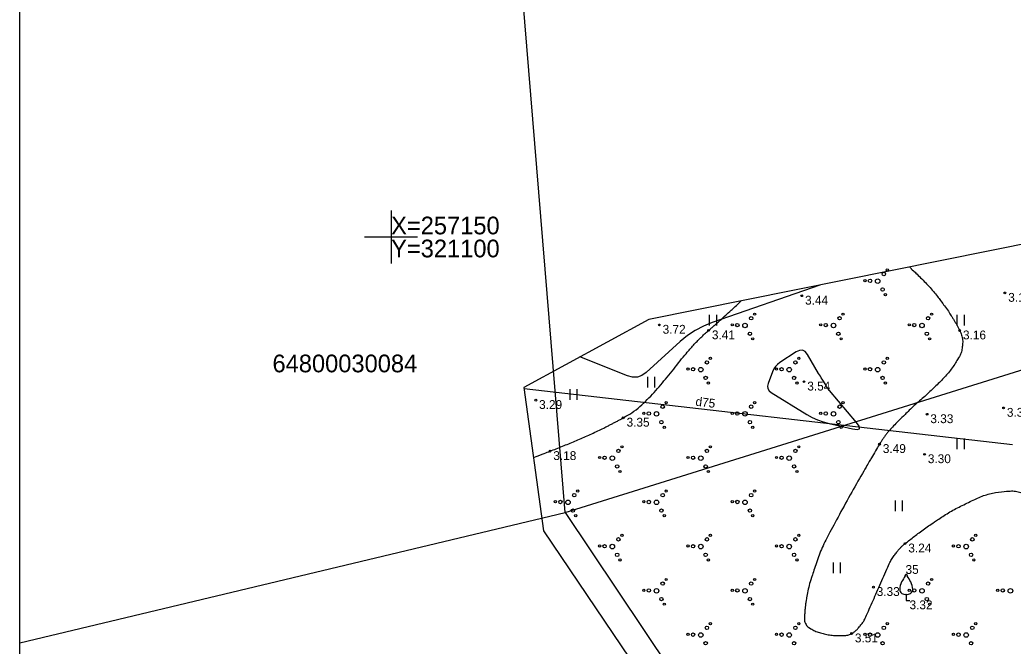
# Model space of a CAD drawing. Extents: x 321079 to 321220, y 257030 to 257220.
# Drawn here: x 321079 to 321135.2, y 257126.9 to 257162.3 of the extents above; entities that cross this region are included whole.
import ezdxf

# ---------------------------------------------------------------- set-up
doc = ezdxf.new("R2010")
doc.units = 0
for name, color, linetype in [('DREN_VADP_####_####_#', 7, 'Continuous'), ('DREN_VADP_####_TKST_#', 7, 'Continuous'), ('GEOD_ELEM_####_####_#', 7, 'Continuous'), ('GEOD_KORD_####_TKST_#', 7, 'Continuous'), ('RAMI_PLAN_####_TKST_#', 7, 'Continuous'), ('RAMI_UZMR_####_####_#', 7, 'Continuous'), ('RELJ_AATZ_####_TKST_#', 7, 'Continuous'), ('RELJ_ELEM_####_####_#', 7, 'Continuous'), ('RELJ_HORZ_PUSH_####_#', 7, 'Continuous'), ('ROBZ_KADS_####_TKST_#', 7, 'Continuous'), ('ROBZ_UZMR_####_####_#', 7, 'Continuous'), ('TERT_DIAM_####_TKST_#', 7, 'Continuous'), ('TERT_ELEM_####_####_#', 7, 'Continuous'), ('TERT_KONT_####_####_#', 7, 'Continuous')]:
    doc.layers.add(name, color=color, linetype=linetype)

msp = doc.modelspace()

# ---------------------------------------------------------------- linework, layer by layer
at = {"layer": 'DREN_VADP_####_####_#'}
msp.add_lwpolyline([(321135.115, 257138.26), (321107.511, 257141.42)], dxfattribs=at)
at = {"layer": 'GEOD_ELEM_####_####_#'}
for p, q in [((321100, 257151.5), (321100, 257150)), ((321098.5, 257150), (321100, 257150)), ((321100, 257150), (321100, 257148.5)), ((321100, 257150), (321101.5, 257150))]:
    msp.add_line(p, q, dxfattribs=at)
at = {"layer": 'RAMI_PLAN_####_TKST_#'}
msp.add_lwpolyline([(321079.019, 257029.866), (321079.019, 257219.866), (321218.314, 257219.866), (321218.314, 257029.866)], close=True, dxfattribs=at)
at = {"layer": 'RAMI_UZMR_####_####_#'}
msp.add_lwpolyline([(321107.5, 257141.5), (321108.611, 257133.395), (321131.584, 257099.382), (321150.327, 257105.322), (321177.121, 257109.842), (321183.308, 257111.386), (321177.517, 257137.442), (321172.561, 257161.05), (321156.27, 257158.872), (321156.852, 257154.517), (321139.352, 257150.329), (321114.57, 257145.337)], close=True, dxfattribs=at)
at = {"layer": 'RELJ_ELEM_####_####_#'}
for centre in [(321123.209, 257146.678), (321134.69, 257146.837), (321115.159, 257145.031), (321117.943, 257144.718), (321132.134, 257144.712), (321123.335, 257141.822), (321108.178, 257140.778), (321134.616, 257140.338), (321113.121, 257139.78), (321130.289, 257139.978), (321127.604, 257138.29), (321108.981, 257137.891), (321130.148, 257137.716), (321129.045, 257132.669), (321127.258, 257130.208), (321126.024, 257127.585)]:
    msp.add_circle(centre, 0.05, dxfattribs=at)
at = {"layer": 'RELJ_HORZ_PUSH_####_#'}
msp.add_lwpolyline([(321124.236, 257147.285), (321118.152, 257145.164), (321117.657, 257144.963), (321117.19, 257144.716), (321116.75, 257144.423), (321116.338, 257144.084), (321114.417, 257142.337), (321114.175, 257142.164), (321113.917, 257142.075), (321113.645, 257142.069), (321113.357, 257142.145), (321110.672, 257143.222)], dxfattribs=at)
msp.add_lwpolyline([(321121.273, 257141.566), (321121.29, 257141.429), (321121.361, 257141.309), (321121.485, 257141.208), (321123.499, 257139.968), (321123.796, 257139.802), (321124.103, 257139.661), (321124.421, 257139.546), (321124.749, 257139.456), (321126.083, 257139.15), (321126.347, 257139.115), (321126.473, 257139.165), (321126.46, 257139.3), (321126.308, 257139.519), (321124.783, 257141.324), (321124.723, 257141.399), (321124.666, 257141.475), (321124.611, 257141.554), (321124.56, 257141.635), (321124.361, 257141.962), (321124.311, 257142.044), (321124.262, 257142.126), (321124.212, 257142.209), (321124.163, 257142.291), (321123.529, 257143.355), (321123.397, 257143.518), (321123.246, 257143.597), (321123.075, 257143.592), (321122.885, 257143.504), (321121.971, 257142.906), (321121.834, 257142.801), (321121.719, 257142.679), (321121.625, 257142.539), (321121.553, 257142.383), (321121.307, 257141.722)], close=True, dxfattribs=at)
at = {"layer": 'ROBZ_UZMR_####_####_#'}
for p, q in [((321109.842, 257134.432), (321104.62, 257197.779)), ((321109.842, 257134.432), (321160.832, 257150.36)), ((321079.019, 257127.063), (321109.842, 257134.432)), ((321109.842, 257134.432), (321131.975, 257101.369))]:
    msp.add_line(p, q, dxfattribs=at)
at = {"layer": 'TERT_ELEM_####_####_#'}
for p, q in [((321118, 257145), (321118, 257145.6)), ((321118.4, 257145), (321118.4, 257145.6)), ((321132, 257145), (321132, 257145.6)), ((321132.4, 257145), (321132.4, 257145.6)), ((321114.5, 257141.5), (321114.5, 257142.1)), ((321114.9, 257141.5), (321114.9, 257142.1)), ((321110.119, 257140.803), (321110.119, 257141.403)), ((321110.519, 257140.803), (321110.519, 257141.403)), ((321132, 257138), (321132, 257138.6)), ((321132.4, 257138), (321132.4, 257138.6)), ((321128.5, 257134.5), (321128.5, 257135.1)), ((321128.9, 257134.5), (321128.9, 257135.1)), ((321125, 257131), (321125, 257131.6)), ((321125.4, 257131), (321125.4, 257131.6)), ((321129.112, 257129.809), (321129.112, 257129.457)), ((321129.112, 257129.457), (321129.312, 257129.457))]:
    msp.add_line(p, q, dxfattribs=at)
for centre, radius in [((321127.848, 257147.908), 0.096), ((321128.044, 257148.139), 0.064), ((321126.782, 257147.534), 0.064), ((321127.066, 257147.521), 0.096), ((321127.5, 257147.5), 0.128), ((321127.776, 257147.033), 0.096), ((321127.934, 257146.744), 0.064), ((321120.348, 257145.408), 0.096), ((321120.544, 257145.639), 0.064), ((321125.348, 257145.408), 0.096), ((321125.544, 257145.639), 0.064), ((321130.348, 257145.408), 0.096), ((321130.544, 257145.639), 0.064), ((321119.282, 257145.034), 0.064), ((321119.566, 257145.021), 0.096), ((321120, 257145), 0.128), ((321124.282, 257145.034), 0.064), ((321124.566, 257145.021), 0.096), ((321125, 257145), 0.128), ((321129.282, 257145.034), 0.064), ((321129.566, 257145.021), 0.096), ((321130, 257145), 0.128), ((321120.276, 257144.533), 0.096), ((321120.434, 257144.244), 0.064), ((321125.276, 257144.533), 0.096), ((321125.434, 257144.244), 0.064), ((321130.276, 257144.533), 0.096), ((321130.434, 257144.244), 0.064), ((321118.044, 257143.139), 0.064), ((321123.044, 257143.139), 0.064), ((321128.044, 257143.139), 0.064), ((321117.066, 257142.521), 0.096), ((321117.5, 257142.5), 0.128), ((321117.848, 257142.908), 0.096), ((321122.066, 257142.521), 0.096), ((321122.5, 257142.5), 0.128), ((321122.848, 257142.908), 0.096), ((321127.066, 257142.521), 0.096), ((321127.5, 257142.5), 0.128), ((321127.848, 257142.908), 0.096), ((321116.782, 257142.534), 0.064), ((321117.776, 257142.033), 0.096), ((321121.782, 257142.534), 0.064), ((321122.776, 257142.033), 0.096), ((321126.782, 257142.534), 0.064), ((321127.776, 257142.033), 0.096), ((321117.934, 257141.744), 0.064), ((321122.934, 257141.744), 0.064), ((321127.934, 257141.744), 0.064), ((321115.348, 257140.408), 0.096), ((321115.544, 257140.639), 0.064), ((321120.348, 257140.408), 0.096), ((321120.544, 257140.639), 0.064), ((321125.348, 257140.408), 0.096), ((321125.544, 257140.639), 0.064), ((321114.282, 257140.034), 0.064), ((321114.566, 257140.021), 0.096), ((321115, 257140), 0.128), ((321119.282, 257140.034), 0.064), ((321119.566, 257140.021), 0.096), ((321120, 257140), 0.128), ((321124.282, 257140.034), 0.064), ((321124.566, 257140.021), 0.096), ((321125, 257140), 0.128), ((321115.276, 257139.533), 0.096), ((321115.434, 257139.244), 0.064), ((321120.276, 257139.533), 0.096), ((321120.434, 257139.244), 0.064), ((321125.276, 257139.533), 0.096), ((321125.434, 257139.244), 0.064), ((321113.044, 257138.139), 0.064), ((321118.044, 257138.139), 0.064), ((321123.044, 257138.139), 0.064), ((321111.782, 257137.534), 0.064), ((321112.066, 257137.521), 0.096), ((321112.5, 257137.5), 0.128), ((321112.848, 257137.908), 0.096), ((321116.782, 257137.534), 0.064), ((321117.066, 257137.521), 0.096), ((321117.5, 257137.5), 0.128), ((321117.848, 257137.908), 0.096), ((321121.782, 257137.534), 0.064), ((321122.066, 257137.521), 0.096), ((321122.5, 257137.5), 0.128), ((321122.848, 257137.908), 0.096), ((321112.776, 257137.033), 0.096), ((321117.776, 257137.033), 0.096), ((321122.776, 257137.033), 0.096), ((321112.934, 257136.744), 0.064), ((321117.934, 257136.744), 0.064), ((321122.934, 257136.744), 0.064), ((321110.348, 257135.408), 0.096), ((321110.544, 257135.639), 0.064), ((321115.348, 257135.408), 0.096), ((321115.544, 257135.639), 0.064), ((321120.348, 257135.408), 0.096), ((321120.544, 257135.639), 0.064), ((321109.282, 257135.034), 0.064), ((321109.566, 257135.021), 0.096), ((321110, 257135), 0.128), ((321114.282, 257135.034), 0.064), ((321114.566, 257135.021), 0.096), ((321115, 257135), 0.128), ((321119.282, 257135.034), 0.064), ((321119.566, 257135.021), 0.096), ((321120, 257135), 0.128), ((321110.276, 257134.533), 0.096), ((321110.434, 257134.244), 0.064), ((321115.276, 257134.533), 0.096), ((321115.434, 257134.244), 0.064), ((321120.276, 257134.533), 0.096), ((321120.434, 257134.244), 0.064), ((321113.044, 257133.139), 0.064), ((321118.044, 257133.139), 0.064), ((321123.044, 257133.139), 0.064), ((321133.044, 257133.139), 0.064), ((321111.782, 257132.534), 0.064), ((321112.066, 257132.521), 0.096), ((321112.5, 257132.5), 0.128), ((321112.848, 257132.908), 0.096), ((321116.782, 257132.534), 0.064), ((321117.066, 257132.521), 0.096), ((321117.5, 257132.5), 0.128), ((321117.848, 257132.908), 0.096), ((321121.782, 257132.534), 0.064), ((321122.066, 257132.521), 0.096), ((321122.5, 257132.5), 0.128), ((321122.848, 257132.908), 0.096), ((321131.782, 257132.534), 0.064), ((321132.066, 257132.521), 0.096), ((321132.5, 257132.5), 0.128), ((321132.848, 257132.908), 0.096), ((321112.776, 257132.033), 0.096), ((321117.776, 257132.033), 0.096), ((321122.776, 257132.033), 0.096), ((321132.776, 257132.033), 0.096), ((321112.934, 257131.744), 0.064), ((321117.934, 257131.744), 0.064), ((321122.934, 257131.744), 0.064), ((321132.934, 257131.744), 0.064), ((321115.348, 257130.408), 0.096), ((321115.544, 257130.639), 0.064), ((321120.348, 257130.408), 0.096), ((321120.544, 257130.639), 0.064), ((321130.348, 257130.408), 0.096), ((321130.544, 257130.639), 0.064), ((321114.282, 257130.034), 0.064), ((321114.566, 257130.021), 0.096), ((321115, 257130), 0.128), ((321119.282, 257130.034), 0.064), ((321119.566, 257130.021), 0.096), ((321120, 257130), 0.128), ((321129.282, 257130.034), 0.064), ((321129.566, 257130.021), 0.096), ((321130, 257130), 0.128), ((321134.282, 257130.034), 0.064), ((321134.566, 257130.021), 0.096), ((321135, 257130), 0.128), ((321115.276, 257129.533), 0.096), ((321115.434, 257129.244), 0.064), ((321120.276, 257129.533), 0.096), ((321120.434, 257129.244), 0.064), ((321130.276, 257129.533), 0.096), ((321130.434, 257129.244), 0.064), ((321118.044, 257128.139), 0.064), ((321123.044, 257128.139), 0.064), ((321128.044, 257128.139), 0.064), ((321133.044, 257128.139), 0.064), ((321116.782, 257127.534), 0.064), ((321117.066, 257127.521), 0.096), ((321117.5, 257127.5), 0.128), ((321117.848, 257127.908), 0.096), ((321121.782, 257127.534), 0.064), ((321122.066, 257127.521), 0.096), ((321122.5, 257127.5), 0.128), ((321122.848, 257127.908), 0.096), ((321126.782, 257127.534), 0.064), ((321127.066, 257127.521), 0.096), ((321127.5, 257127.5), 0.128), ((321127.848, 257127.908), 0.096), ((321131.782, 257127.534), 0.064), ((321132.066, 257127.521), 0.096), ((321132.5, 257127.5), 0.128), ((321132.848, 257127.908), 0.096), ((321117.776, 257127.033), 0.096), ((321122.776, 257127.033), 0.096), ((321127.776, 257127.033), 0.096), ((321132.776, 257127.033), 0.096)]:
    msp.add_circle(centre, radius, dxfattribs=at)
for centre, radius, start, end in [((321141.737, 257123.061), 14.88, 148.4844, 149.9901), ((321128.695, 257131.095), 0.439, 324.3837, 341.712), ((321129.529, 257131.095), 0.439, 198.288, 215.6163), ((321116.487, 257123.061), 14.88, 30.0099, 31.5156), ((321129.636, 257130.082), 0.89, 151.757, 179.9138), ((321128.588, 257130.082), 0.89, 0.0862, 28.243), ((321129.036, 257130.088), 0.29, 181.0782, 285.2823), ((321129.188, 257130.088), 0.29, 254.7177, 358.9218)]:
    msp.add_arc(centre, radius, start, end, dxfattribs=at)
at = {"layer": 'TERT_KONT_####_####_#'}
for points in [[(321129.296, 257148.304), (321129.341, 257148.261), (321129.386, 257148.219), (321129.431, 257148.175), (321129.997, 257147.629), (321130.535, 257147.084), (321131.007, 257146.464), (321131.229, 257146.173), (321131.445, 257145.88), (321131.641, 257145.571), (321131.732, 257145.427), (321131.822, 257145.282), (321131.907, 257145.134), (321131.947, 257145.064), (321131.986, 257144.992), (321132.026, 257144.921), (321132.063, 257144.852), (321132.099, 257144.783), (321132.134, 257144.712), (321132.197, 257144.587), (321132.235, 257144.453), (321132.271, 257144.317), (321132.304, 257144.188), (321132.307, 257144.052), (321132.294, 257143.922), (321132.267, 257143.648), (321132.204, 257143.378), (321132.049, 257143.129), (321131.664, 257142.512), (321131.238, 257142.013), (321130.74, 257141.535), (321130.167, 257140.985), (321129.559, 257140.48), (321128.996, 257139.924), (321128.727, 257139.659), (321128.461, 257139.391), (321128.207, 257139.11), (321128.089, 257138.98), (321127.978, 257138.844), (321127.876, 257138.701), (321127.78, 257138.567), (321127.689, 257138.431), (321127.604, 257138.29), (321127.372, 257137.904), (321127.146, 257137.516), (321126.921, 257137.126), (321126.204, 257135.885), (321125.508, 257134.637), (321124.83, 257133.371), (321124.395, 257132.558), (321124.066, 257131.698), (321123.781, 257130.816), (321123.649, 257130.407), (321123.546, 257129.995), (321123.474, 257129.573), (321123.44, 257129.372), (321123.41, 257129.171), (321123.392, 257128.968), (321123.382, 257128.868), (321123.376, 257128.769), (321123.37, 257128.67), (321123.364, 257128.572), (321123.362, 257128.474), (321123.363, 257128.376), (321123.363, 257128.279), (321123.397, 257128.188), (321123.453, 257128.099), (321123.517, 257127.997), (321123.596, 257127.929), (321123.697, 257127.871), (321123.95, 257127.726), (321124.201, 257127.63), (321124.477, 257127.566), (321124.773, 257127.498), (321125.07, 257127.468), (321125.365, 257127.469), (321125.586, 257127.469), (321125.807, 257127.489), (321126.024, 257127.585), (321126.11, 257127.623), (321126.176, 257127.675), (321126.244, 257127.735), (321126.317, 257127.8), (321126.385, 257127.864), (321126.446, 257127.94), (321126.585, 257128.113), (321126.721, 257128.288), (321126.81, 257128.488), (321127.025, 257128.97), (321127.24, 257129.453), (321127.454, 257129.935), (321127.682, 257130.449), (321127.909, 257130.964), (321128.138, 257131.479), (321128.244, 257131.718), (321128.394, 257131.934), (321128.552, 257132.146), (321128.662, 257132.293), (321128.779, 257132.43), (321128.913, 257132.555), (321128.956, 257132.595), (321128.999, 257132.633), (321129.045, 257132.669), (321129.307, 257132.877), (321129.57, 257133.08), (321129.838, 257133.28), (321130.141, 257133.505), (321130.45, 257133.717), (321130.763, 257133.93), (321131.417, 257134.374), (321132.085, 257134.734), (321132.823, 257135.088), (321133.478, 257135.403), (321134.165, 257135.57), (321134.85, 257135.629), (321135.141, 257135.654), (321135.444, 257135.606), (321135.734, 257135.506), (321135.875, 257135.457), (321136.001, 257135.399), (321136.124, 257135.317), (321136.251, 257135.233), (321136.366, 257135.144), (321136.47, 257135.034), (321136.693, 257134.798), (321136.896, 257134.556), (321137.073, 257134.288), (321137.256, 257134.01), (321137.432, 257133.732), (321137.583, 257133.438), (321137.739, 257133.135), (321137.891, 257132.832), (321138.033, 257132.524), (321138.177, 257132.212), (321138.309, 257131.894), (321138.456, 257131.583), (321138.59, 257131.301), (321138.733, 257131.023), (321138.869, 257130.742), (321139.009, 257130.456), (321139.139, 257130.17), (321139.267, 257129.874), (321139.384, 257129.605), (321139.444, 257129.316), (321139.472, 257129.03), (321139.485, 257128.899), (321139.474, 257128.764), (321139.446, 257128.633), (321139.433, 257128.568), (321139.415, 257128.506), (321139.391, 257128.443), (321139.367, 257128.38), (321139.34, 257128.32), (321139.305, 257128.261), (321139.147, 257127.999), (321138.966, 257127.764), (321138.743, 257127.556), (321138.511, 257127.34), (321138.274, 257127.139), (321138.012, 257126.967), (321137.742, 257126.789), (321137.472, 257126.612), (321137.197, 257126.441), (321137.059, 257126.356), (321136.921, 257126.272), (321136.784, 257126.186), (321136.648, 257126.102), (321136.516, 257126.013), (321136.381, 257125.928), (321136.104, 257125.753), (321135.818, 257125.594), (321135.521, 257125.454), (321135.219, 257125.311), (321134.907, 257125.196), (321134.594, 257125.083), (321133.961, 257124.856), (321133.312, 257124.683), (321132.677, 257124.46), (321132.063, 257124.245), (321131.471, 257123.99), (321130.897, 257123.67), (321130.617, 257123.514), (321130.371, 257123.316), (321130.143, 257123.092), (321130.026, 257122.978), (321129.916, 257122.862), (321129.814, 257122.736), (321129.763, 257122.671), (321129.713, 257122.606), (321129.664, 257122.538), (321129.615, 257122.47), (321129.568, 257122.4), (321129.524, 257122.327), (321129.259, 257121.895), (321129.047, 257121.444), (321128.858, 257120.971), (321128.674, 257120.511), (321128.527, 257120.045), (321128.449, 257119.559), (321128.293, 257118.586), (321128.187, 257117.612), (321128.124, 257116.631), (321128.06, 257115.644), (321128.061, 257114.653), (321127.991, 257113.666), (321127.956, 257113.177), (321127.906, 257112.691), (321127.823, 257112.207), (321127.74, 257111.725), (321127.638, 257111.249), (321127.494, 257110.784), (321127.116, 257109.561), (321126.739, 257108.338), (321126.361, 257107.115)], [(321108.045, 257137.526), (321108.357, 257137.648), (321108.669, 257137.769), (321108.981, 257137.891), (321109.334, 257138.029), (321109.685, 257138.171), (321110.037, 257138.314), (321110.388, 257138.457), (321110.735, 257138.608), (321111.081, 257138.763), (321111.427, 257138.919), (321111.77, 257139.081), (321112.11, 257139.249), (321112.281, 257139.333), (321112.449, 257139.421), (321112.618, 257139.508), (321112.788, 257139.596), (321112.955, 257139.686), (321113.121, 257139.78), (321113.614, 257140.058), (321114.073, 257140.398), (321114.47, 257140.806), (321114.87, 257141.215), (321115.24, 257141.642), (321115.602, 257142.081), (321115.973, 257142.531), (321116.324, 257142.995), (321116.699, 257143.441), (321116.889, 257143.667), (321117.084, 257143.889), (321117.291, 257144.1), (321117.501, 257144.314), (321117.718, 257144.52), (321117.943, 257144.718), (321118.022, 257144.788), (321118.103, 257144.855), (321118.182, 257144.925), (321118.423, 257145.14), (321118.665, 257145.356), (321118.904, 257145.573), (321119.201, 257145.843), (321119.493, 257146.117), (321119.788, 257146.389)]]:
    msp.add_open_spline(points, degree=3, dxfattribs=at)

# ---------------------------------------------------------------- texts
at = {"layer": 'DREN_VADP_####_TKST_#'}
msp.add_text('d75', height=0.5, rotation=353.4688, dxfattribs=at).set_placement((321117.182, 257140.464))
at = {"layer": 'GEOD_KORD_####_TKST_#'}
for s, p in [('X=257150', (321100, 257150.15)), ('Y=321100', (321100, 257148.85))]:
    msp.add_text(s, height=1, dxfattribs=at).set_placement(p)
at = {"layer": 'RELJ_AATZ_####_TKST_#'}
for s, p in [(' 3.44', (321123.209, 257146.178)), (' 3.11', (321134.69, 257146.337)), (' 3.72', (321115.159, 257144.531)), (' 3.41', (321117.943, 257144.218)), (' 3.16', (321132.134, 257144.212)), (' 3.54', (321123.335, 257141.322)), (' 3.29', (321108.178, 257140.278)), (' 3.33', (321130.289, 257139.478)), (' 3.33', (321134.616, 257139.838)), (' 3.35', (321113.121, 257139.28)), (' 3.49', (321127.604, 257137.79)), (' 3.18', (321108.981, 257137.391)), (' 3.30', (321130.148, 257137.216)), (' 3.24', (321129.045, 257132.169)), (' 3.33', (321127.258, 257129.708)), (' 3.32', (321129.112, 257128.957)), (' 3.51', (321126.024, 257127.085))]:
    msp.add_text(s, height=0.5, dxfattribs=at).set_placement(p)
at = {"layer": 'ROBZ_KADS_####_TKST_#'}
msp.add_text('64800030084', height=1, dxfattribs=at).set_placement((321093.295, 257142.351))
at = {"layer": 'TERT_DIAM_####_TKST_#'}
msp.add_text(' 35', height=0.5, dxfattribs=at).set_placement((321128.887, 257130.957))

doc.saveas('drawing.dxf')
